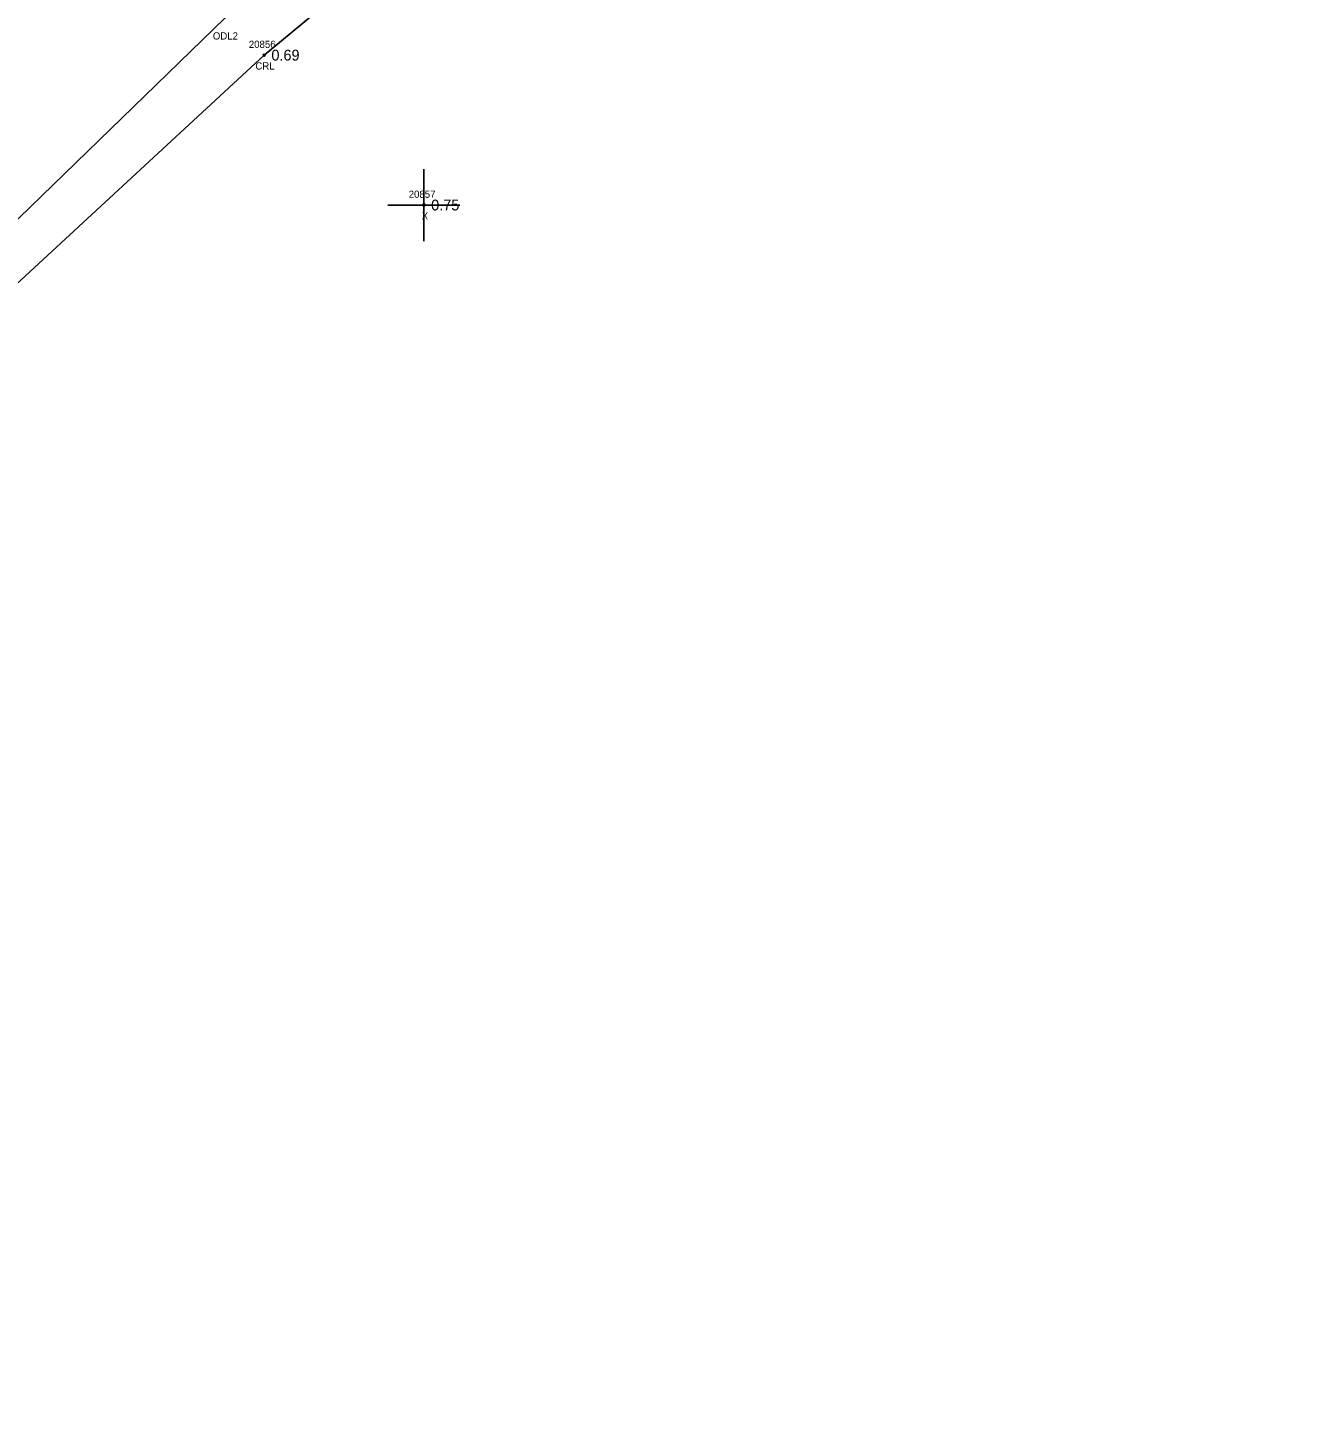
# Model space of a CAD drawing. Extents: x 2608745 to 2610333, y 641917 to 643463.
# Drawn here: x 2609764.9 to 2609943.8, y 642658.2 to 642851.5 of the extents above; entities that cross this region are included whole.
import ezdxf

# ---------------------------------------------------------------- set-up
doc = ezdxf.new("R2010")
doc.units = 0
for name, color, linetype in [('RD_EX_H2O', 7, 'Continuous'), ('RD_EX_H2O_txCode', 7, 'Continuous'), ('RD_EX_Misc', 7, 'Continuous'), ('RD_EX_Misc_txCode', 7, 'Continuous'), ('RD_EX_TX_H2O_ELEV', 7, 'Continuous'), ('RD_EX_TX_Misc_ELEV', 7, 'Continuous'), ('RD_SMD_Locator', 7, 'Continuous')]:
    doc.layers.add(name, color=color, linetype=linetype)

msp = doc.modelspace()

# ---------------------------------------------------------------- linework, layer by layer
at = {"layer": 'RD_EX_H2O'}
for points in [[(2609940.72, 642981.52), (2609865.8, 642912.86), (2609792.29, 642852.87), (2609723.77, 642786.36), (2609663.25, 642717.18), (2609610.37, 642689.46), (2609581.45, 642670.47), (2609545.26, 642637.18), (2609509.19, 642582.86), (2609482.73, 642569.2), (2609408.72, 642506.3), (2609370.25, 642508.5), (2609327.7, 642455.81), (2609283.83, 642369.21), (2609262.12, 642251.22)], [(2609943.79, 642976.05), (2609869.55, 642907.14), (2609797.73, 642847.7), (2609725.24, 642780.75), (2609667.97, 642714.2), (2609673.28, 642700.22), (2609713.56, 642689.91), (2609733.33, 642661.98), (2609719.28, 642638.68), (2609663.61, 642631.91), (2609659.09, 642626.02), (2609711.84, 642571.44), (2609760.21, 642528.21), (2609792.62, 642516.23), (2609800.76, 642528.12), (2609797.45, 642563.99), (2609816.12, 642605.87)]]:
    msp.add_lwpolyline(points, dxfattribs=at)
at = {"layer": 'RD_EX_Misc'}
for p, q in [((2609819.91, 642821.89), (2609819.91, 642831.89)), ((2609814.91, 642826.89), (2609824.91, 642826.89))]:
    msp.add_line(p, q, dxfattribs=at)
at = {"layer": 'RD_SMD_Locator'}
for centre in [(2609797.73, 642847.7), (2609819.91, 642826.89)]:
    msp.add_circle(centre, 0.15, dxfattribs=at)

# ---------------------------------------------------------------- texts
at = {"layer": 'RD_EX_H2O_txCode'}
for s, p in [('ODL2', (2609790.59, 642849.87)), ('20856', (2609795.59, 642848.7)), ('CRL', (2609796.5, 642845.7))]:
    msp.add_text(s, height=1, dxfattribs=at).set_placement(p)
at = {"layer": 'RD_EX_Misc_txCode'}
for s, p in [('20857', (2609817.79, 642827.89)), ('X', (2609819.59, 642824.89))]:
    msp.add_text(s, height=1, dxfattribs=at).set_placement(p)
at = {"layer": 'RD_EX_TX_H2O_ELEV'}
msp.add_text('0.69', height=1.5, dxfattribs=at).set_placement((2609798.73, 642846.95))
at = {"layer": 'RD_EX_TX_Misc_ELEV'}
msp.add_text('0.75', height=1.5, dxfattribs=at).set_placement((2609820.91, 642826.14))

doc.saveas('drawing.dxf')
